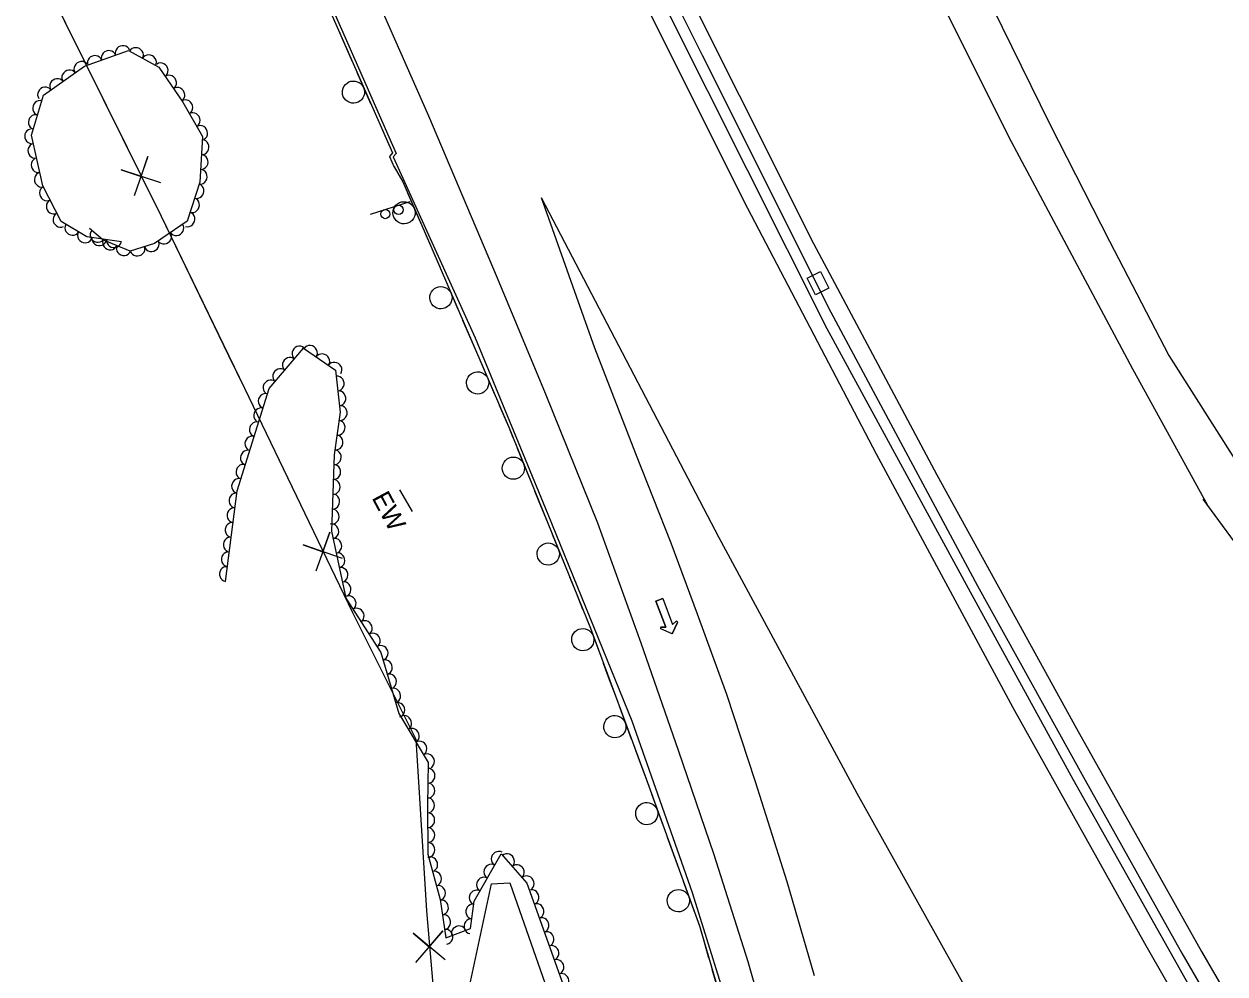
# Model space of a CAD drawing. Extents: x 1746719 to 1766531, y 631721 to 662391.
# Drawn here: x 1764151.5 to 1764475.4, y 633278.6 to 633534.8 of the extents above; entities that cross this region are included whole.
import ezdxf

# ---------------------------------------------------------------- set-up
doc = ezdxf.new("R2010")
doc.units = 0
for name, color, linetype in [('SURVEY - AERIAL SURVEY - Photo Control - Points - Elevations', 7, 'Continuous'), ('SURVEY - AERIAL SURVEY - Photo Control - Points - Locators', 7, 'Continuous'), ('SURVEY - AERIAL SURVEY - Photo Control - Points - Numbers', 7, 'Continuous'), ('SURVEY - AERIAL SURVEY - Photo Control with Text', 7, 'Continuous'), ('SURVEY - CENTERLINE - Existing Roads Curve Text', 7, 'Continuous'), ('SURVEY - CENTERLINE - Existing Roads Text', 7, 'Continuous'), ('SURVEY - CENTERLINE - Preliminary - Development', 7, 'Continuous'), ('SURVEY - CENTERLINE - Preliminary Curve Text', 7, 'Continuous'), ('SURVEY - CONTROL - Grid', 7, 'Continuous')]:
    doc.layers.add(name, color=color, linetype=linetype)

msp = doc.modelspace()

# ---------------------------------------------------------------- linework, layer by layer
at = {"layer": 'SURVEY - AERIAL SURVEY - Photo Control - Points - Elevations'}
for points in [[(1764348.8, 633669.24), (1764389.59, 633586.37), (1764428.15, 633507.81), (1764444.24, 633476.22), (1764460.26, 633445.38)], [(1764180.93, 633660.56), (1764237.06, 633533.45), (1764251.85, 633499.9), (1764251.04, 633498.94), (1764273.17, 633450.19), (1764292.77, 633402.64), (1764315.39, 633346.9), (1764331.65, 633300.6), (1764347.14, 633250.91), (1764359.02, 633206.16), (1764363.95, 633185.33), (1764368.51, 633162.04), (1764371.67, 633132.89), (1764372.54, 633100.95), (1764372.37, 633061.95), (1764369.93, 633023.67), (1764365.45, 632984.07)], [(1764340.8, 633658.6), (1764378.13, 633582.34), (1764417.77, 633503.15), (1764450.46, 633441.79), (1764470.69, 633405.08)], [(1764286.91, 633632.22), (1764324.36, 633555.72), (1764364.46, 633475.61), (1764397.7, 633413.21), (1764435.38, 633344.82), (1764469.06, 633284.69), (1764504.2, 633224.1), (1764542.48, 633159.48), (1764578.77, 633099.35), (1764616.47, 633039.95), (1764651.83, 632984.84), (1764692.24, 632923.64), (1764727.21, 632872.71), (1764758.15, 632827.22), (1764788.79, 632783.76), (1764825.53, 632732.1), (1764845.75, 632704.38)], [(1764831.69, 632702.44), (1764811.98, 632730.49), (1764779.64, 632775.81), (1764755.56, 632810.46), (1764723.74, 632856.23), (1764690.96, 632904.23), (1764661.37, 632949.17), (1764640.02, 632981.61), (1764615.9, 633018.34), (1764577.35, 633078.68), (1764534.79, 633147.94), (1764491.74, 633220.52), (1764453.8, 633286.81), (1764418.29, 633350.37), (1764381.37, 633418.77), (1764346.73, 633485.01), (1764310.57, 633557.37), (1764276.55, 633626.71)], [(1764375.62, 633017.64), (1764377.11, 633036.06), (1764378.16, 633054.7), (1764378.58, 633076.59), (1764378.28, 633098.77), (1764377.03, 633120.24), (1764375.76, 633139.47), (1764373.54, 633158.27), (1764370.32, 633178.81), (1764365.78, 633204.96), (1764360.5, 633229.86), (1764354.37, 633255.4), (1764346.8, 633281.9), (1764337.58, 633310.69), (1764327.99, 633338.84), (1764317.96, 633367.8), (1764306.25, 633400.14), (1764292.1, 633435.15), (1764279.15, 633466.29), (1764260.67, 633509.91), (1764240.97, 633554.63), (1764224.98, 633591.65)], [(1764364.68, 633278.08), (1764357.33, 633303.48), (1764348.81, 633330.39), (1764341.06, 633353.93), (1764333.11, 633375.62), (1764326, 633394.77), (1764316.48, 633418.88), (1764305.41, 633447.36), (1764291.02, 633487.95)], [(1764777.7, 632695.9), (1764740.39, 632748.17), (1764716.15, 632783.07), (1764684.21, 632828.99), (1764651.09, 632877.5), (1764621.28, 632922.78), (1764599.91, 632955.24), (1764575.61, 632992.25), (1764536.68, 633053.19), (1764493.7, 633123.13), (1764450.26, 633196.35), (1764412.02, 633263.19), (1764376.22, 633327.26), (1764338.98, 633396.24), (1764291.02, 633487.95)], [(1764460.26, 633445.38), (1764503.08, 633378.08)], [(1764563.3, 633279.03), (1764469.51, 633406.68)]]:
    msp.add_lwpolyline(points, dxfattribs=at)
at = {"layer": 'SURVEY - AERIAL SURVEY - Photo Control - Points - Locators'}
for p, q in [((1764321.92, 633379.17), (1764323.76, 633379.86)), ((1764323.76, 633379.86), (1764321.92, 633379.17)), ((1764324.58, 633372.13), (1764321.92, 633379.17)), ((1764321.92, 633379.17), (1764324.58, 633372.13)), ((1764323.76, 633379.86), (1764326.42, 633372.83)), ((1764323.76, 633379.86), (1764326.42, 633372.83)), ((1764323.35, 633372.17), (1764324.58, 633372.13)), ((1764324.58, 633372.13), (1764323.35, 633372.17)), ((1764327.71, 633373.39), (1764326.32, 633370.31)), ((1764326.32, 633370.31), (1764327.71, 633373.39)), ((1764326.42, 633372.83), (1764327.32, 633373.67)), ((1764326.42, 633372.83), (1764327.32, 633373.67)), ((1764326.32, 633370.31), (1764323.25, 633371.7)), ((1764326.32, 633370.31), (1764323.25, 633371.7))]:
    msp.add_line(p, q, dxfattribs=at)
msp.add_lwpolyline([(1764217.52, 632950.86), (1764233.96, 633053.68), (1764238.22, 633178.73), (1764251.95, 633231.92), (1764269.77, 633266.37), (1764277.54, 633302.92), (1764282.55, 633303.21), (1764295.22, 633266.91), (1764297.88, 633268.26), (1764313.8, 633246.32), (1764333.81, 633245.93), (1764340.96, 633234.86), (1764349.07, 633222.31), (1764363.07, 633166.36), (1764365.96, 633113.65), (1764366.58, 633060.3), (1764362.57, 633002.69)], dxfattribs=at)
for centre, start, end in [((1764323.35, 633371.92), 88.2612, 245.7095), ((1764323.35, 633371.92), 88.2612, 245.7095), ((1764327.49, 633373.49), 335.7095, 133.2026), ((1764327.49, 633373.49), 335.7095, 133.2026)]:
    msp.add_arc(centre, 0.246, start, end, dxfattribs=at)
at = {"layer": 'SURVEY - AERIAL SURVEY - Photo Control - Points - Numbers'}
for points in [[(1764180.13, 633660.21), (1764236.26, 633533.1), (1764250.83, 633500.04), (1764250.02, 633499.07), (1764251.32, 633496.19)], [(1764837.81, 632703.35), (1764810.72, 632740.31), (1764770.99, 632796.4), (1764726.66, 632860.1), (1764677.61, 632931.8), (1764621.09, 633019), (1764574.03, 633093.64), (1764526.02, 633172.29), (1764474.29, 633260.27), (1764434.46, 633331.05), (1764406.76, 633381.58), (1764368.12, 633452.62), (1764325.13, 633538.21), (1764281.43, 633628.12)], [(1764283.41, 633629.46), (1764296.35, 633602.51), (1764334.35, 633526.38), (1764369.12, 633457.05), (1764408.67, 633383.28), (1764437.22, 633331.71), (1764463.82, 633284.24), (1764490.85, 633237.46), (1764535.54, 633161.37), (1764569.37, 633106.49), (1764606.28, 633047.19), (1764645.68, 632986.22), (1764676.08, 632939.9), (1764709.83, 632889.53), (1764732.42, 632856.58), (1764758.21, 632819.17), (1764787.18, 632777.39), (1764806.45, 632750.71), (1764840.69, 632703.63)], [(1764236.16, 633533.34), (1764236.26, 633533.1), (1764238.05, 633529.04)], [(1764238.05, 633529.04), (1764239.95, 633524.73)], [(1764241.24, 633521.81), (1764244.95, 633513.39)], [(1764246.24, 633510.46), (1764248.13, 633506.16)], [(1764248.13, 633506.16), (1764250.03, 633501.86)], [(1764250.04, 633499.11), (1764250.02, 633499.08), (1764251.32, 633496.19)], [(1764251.28, 633496.28), (1764253.61, 633492.24), (1764261.18, 633474.91), (1764282.22, 633426.03), (1764304.24, 633371.87), (1764319.24, 633331.22), (1764333.63, 633291.54), (1764344.61, 633253.99), (1764354.34, 633219.42), (1764359.53, 633197.55), (1764364.8, 633173.55), (1764367.86, 633154.62), (1764369.32, 633137.18), (1764371, 633110.32), (1764371.64, 633083.85), (1764371.62, 633060.38), (1764370, 633036.65), (1764367.74, 633012.27)], [(1764251.28, 633496.28), (1764253.61, 633492.24), (1764253.62, 633492.2)], [(1764254.9, 633489.27), (1764258.59, 633480.84)], [(1764259.87, 633477.91), (1764261.18, 633474.91), (1764261.75, 633473.6)], [(1764261.75, 633473.6), (1764263.6, 633469.28)], [(1764264.87, 633466.34), (1764268.51, 633457.89)], [(1764269.77, 633454.95), (1764271.63, 633450.64)], [(1764271.63, 633450.64), (1764273.49, 633446.32)], [(1764274.75, 633443.38), (1764278.39, 633434.93)], [(1764279.65, 633431.99), (1764281.51, 633427.67)], [(1764281.51, 633427.67), (1764282.22, 633426.03), (1764283.32, 633423.33)], [(1764284.52, 633420.37), (1764287.99, 633411.84)], [(1764289.19, 633408.88), (1764290.96, 633404.53)], [(1764290.96, 633404.53), (1764292.73, 633400.17)], [(1764293.94, 633397.21), (1764297.4, 633388.69)], [(1764298.61, 633385.72), (1764300.38, 633381.37)], [(1764300.38, 633381.37), (1764302.15, 633377.01)], [(1764303.35, 633374.05), (1764304.24, 633371.87), (1764306.61, 633365.45)], [(1764307.72, 633362.44), (1764309.34, 633358.03)], [(1764309.34, 633358.03), (1764310.97, 633353.62)], [(1764312.08, 633350.62), (1764315.27, 633341.99)], [(1764316.37, 633338.99), (1764318, 633334.58)], [(1764318, 633334.58), (1764319.24, 633331.22), (1764319.62, 633330.17)], [(1764320.71, 633327.16), (1764323.85, 633318.51)], [(1764324.94, 633315.5), (1764326.54, 633311.08)], [(1764326.54, 633311.08), (1764328.15, 633306.67)], [(1764329.24, 633303.66), (1764332.37, 633295.01)], [(1764333.46, 633292), (1764333.63, 633291.54), (1764334.81, 633287.5)], [(1764334.81, 633287.5), (1764336.13, 633282.99)], [(1764337.03, 633279.92), (1764339.61, 633271.09)]]:
    msp.add_lwpolyline(points, dxfattribs=at)
for centre, start, end in [((1764240.33, 633516.43), 137.0484, 137.0344), ((1764253.98, 633483.89), 136.8821, 136.8681), ((1764263.91, 633460.97), 136.5547, 136.5408), ((1764273.8, 633438.01), 136.5547, 136.5408), ((1764283.46, 633415.02), 135.3926, 135.3786), ((1764292.87, 633391.86), 135.3926, 135.3786), ((1764302.19, 633368.76), 133.5282, 133.5142), ((1764310.84, 633345.31), 133.5282, 133.5142), ((1764319.45, 633321.86), 133.2013, 133.1873), ((1764327.97, 633298.35), 133.2013, 133.1873)]:
    msp.add_arc(centre, 3, start, end, dxfattribs=at)
at = {"layer": 'SURVEY - AERIAL SURVEY - Photo Control with Text'}
for points in [[(1764177.71, 633476.1), (1764168.44, 633477.37), (1764161.45, 633481.53), (1764156.52, 633491.16), (1764153.47, 633504.81), (1764156.75, 633515.62), (1764167.8, 633523.42), (1764179.6, 633527.63), (1764187.86, 633523.12), (1764194.29, 633513.7), (1764199.63, 633504.46), (1764198.87, 633492.14), (1764195.48, 633481.65), (1764186.66, 633475.59), (1764180.11, 633473.52), (1764172.75, 633476.59), (1764169.12, 633479.63)], [(1764205.81, 633384.48), (1764208.96, 633408.94), (1764217.59, 633436.47), (1764226.88, 633447.39), (1764235.52, 633441.46), (1764236.77, 633430.14), (1764235.15, 633418.62), (1764234.44, 633398.06), (1764238.26, 633379.96), (1764247.74, 633365.27), (1764252.55, 633348.89), (1764260.47, 633335.63), (1764260.31, 633324.09), (1764260.4, 633310.87), (1764263.71, 633298.68), (1764265.28, 633288.34), (1764271.93, 633290.88), (1764272.88, 633298.21), (1764280.16, 633310.97), (1764287.12, 633303.1), (1764298.26, 633271.93)]]:
    msp.add_lwpolyline(points, dxfattribs=at)
for centre, major_axis in [((1764174.29, 633525.74), (1.88, 0.67)), ((1764178.05, 633527.08), (1.88, 0.67)), ((1764181.67, 633526.5), (1.76, -0.96)), ((1764166.89, 633522.78), (1.63, 1.15)), ((1764170.52, 633524.39), (1.88, 0.67)), ((1764185.18, 633524.58), (1.76, -0.96)), ((1764188.4, 633522.34), (1.13, -1.65)), ((1764163.62, 633520.47), (1.63, 1.15)), ((1764190.65, 633519.04), (1.13, -1.65)), ((1764157.09, 633515.86), (1.63, 1.15)), ((1764160.36, 633518.16), (1.63, 1.15)), ((1764192.91, 633515.73), (1.13, -1.65)), ((1764195.06, 633512.37), (1, -1.73)), ((1764155.71, 633512.18), (0.58, 1.91)), ((1764154.55, 633508.36), (0.58, 1.91)), ((1764197.06, 633508.9), (1, -1.73)), ((1764153.53, 633504.52), (-0.44, 1.95)), ((1764199.06, 633505.44), (1, -1.73)), ((1764154.41, 633500.62), (-0.44, 1.95)), ((1764199.45, 633501.6), (-0.12, -2)), ((1764155.28, 633496.72), (-0.44, 1.95)), ((1764199.21, 633497.6), (-0.12, -2)), ((1764198.96, 633493.61), (-0.12, -2)), ((1764156.15, 633492.81), (-0.44, 1.95)), ((1764157.57, 633489.11), (-0.91, 1.78)), ((1764198.1, 633489.74), (-0.62, -1.9)), ((1764159.39, 633485.55), (-0.91, 1.78)), ((1764196.87, 633485.93), (-0.62, -1.9)), ((1764161.21, 633481.99), (-0.91, 1.78)), ((1764195.64, 633482.13), (-0.62, -1.9)), ((1764164.45, 633479.75), (-1.72, 1.02)), ((1764171.25, 633477.85), (-1.53, 1.28)), ((1764192.6, 633479.67), (-1.65, -1.13)), ((1764167.88, 633477.7), (-1.72, 1.02)), ((1764171.76, 633476.91), (-1.98, 0.27)), ((1764174.64, 633475.8), (-1.85, 0.77)), ((1764175.72, 633476.37), (-1.98, 0.27)), ((1764185.9, 633475.35), (-1.91, -0.6)), ((1764189.3, 633477.41), (-1.65, -1.13)), ((1764178.33, 633474.26), (-1.85, 0.77)), ((1764182.08, 633474.14), (-1.91, -0.6)), ((1764225.68, 633445.98), (1.3, 1.52)), ((1764228.65, 633446.18), (1.65, -1.13)), ((1764223.09, 633442.93), (1.3, 1.52)), ((1764231.95, 633443.91), (1.65, -1.13)), ((1764235.24, 633441.65), (1.65, -1.13)), ((1764220.49, 633439.89), (1.3, 1.52)), ((1764217.9, 633436.84), (1.3, 1.52)), ((1764235.92, 633437.82), (0.22, -1.99)), ((1764216.54, 633433.12), (0.6, 1.91)), ((1764236.36, 633433.84), (0.22, -1.99)), ((1764215.34, 633429.3), (0.6, 1.91)), ((1764236.73, 633429.87), (-0.28, -1.98)), ((1764214.14, 633425.48), (0.6, 1.91)), ((1764236.18, 633425.91), (-0.28, -1.98)), ((1764235.62, 633421.95), (-0.28, -1.98)), ((1764212.95, 633421.66), (0.6, 1.91)), ((1764211.75, 633417.85), (0.6, 1.91)), ((1764235.13, 633417.98), (-0.07, -2)), ((1764210.55, 633414.03), (0.6, 1.91)), ((1764234.99, 633413.98), (-0.07, -2)), ((1764209.36, 633410.21), (0.6, 1.91)), ((1764234.85, 633409.98), (-0.07, -2)), ((1764208.62, 633406.3), (0.25, 1.98)), ((1764234.71, 633405.99), (-0.07, -2)), ((1764208.11, 633402.33), (0.25, 1.98)), ((1764234.58, 633401.99), (-0.07, -2)), ((1764207.6, 633398.36), (0.25, 1.98)), ((1764234.45, 633397.99), (0.41, -1.96)), ((1764207.09, 633394.4), (0.25, 1.98)), ((1764235.28, 633394.08), (0.41, -1.96)), ((1764206.58, 633390.43), (0.25, 1.98)), ((1764236.1, 633390.17), (0.41, -1.96)), ((1764206.07, 633386.46), (0.25, 1.98)), ((1764236.93, 633386.25), (0.41, -1.96)), ((1764237.76, 633382.34), (0.41, -1.96)), ((1764239.11, 633378.64), (1.08, -1.68)), ((1764241.28, 633375.28), (1.08, -1.68)), ((1764243.45, 633371.92), (1.08, -1.68)), ((1764245.62, 633368.56), (1.08, -1.68)), ((1764247.76, 633365.19), (0.56, -1.92)), ((1764248.89, 633361.35), (0.56, -1.92)), ((1764250.02, 633357.51), (0.56, -1.92)), ((1764251.14, 633353.67), (0.56, -1.92)), ((1764252.27, 633349.84), (0.56, -1.92)), ((1764254.09, 633346.3), (1.03, -1.72)), ((1764256.15, 633342.87), (1.03, -1.72)), ((1764258.2, 633339.43), (1.03, -1.72)), ((1764260.25, 633336), (1.03, -1.72)), ((1764260.42, 633332.06), (-0.03, -2)), ((1764260.37, 633328.06), (-0.03, -2)), ((1764260.31, 633324.06), (0.01, -2)), ((1764260.34, 633320.06), (0.01, -2)), ((1764260.37, 633316.06), (0.01, -2)), ((1764260.39, 633312.06), (0.01, -2)), ((1764279.42, 633309.68), (0.99, 1.74)), ((1764281.82, 633309.09), (1.32, -1.5)), ((1764261.14, 633308.16), (0.52, -1.93)), ((1764277.44, 633306.2), (0.99, 1.74)), ((1764284.47, 633306.1), (1.32, -1.5)), ((1764262.19, 633304.3), (0.52, -1.93)), ((1764275.46, 633302.73), (0.99, 1.74)), ((1764287.12, 633303.1), (1.32, -1.5)), ((1764263.23, 633300.44), (0.52, -1.93)), ((1764273.48, 633299.25), (0.99, 1.74)), ((1764288.47, 633299.33), (0.67, -1.88)), ((1764264.04, 633296.53), (0.3, -1.98)), ((1764272.52, 633295.44), (0.26, 1.98)), ((1764289.81, 633295.57), (0.67, -1.88)), ((1764264.64, 633292.57), (0.3, -1.98)), ((1764268.75, 633289.66), (1.87, 0.71)), ((1764272.01, 633291.47), (0.26, 1.98)), ((1764291.16, 633291.8), (0.67, -1.88)), ((1764265.24, 633288.62), (0.3, -1.98)), ((1764292.51, 633288.03), (0.67, -1.88)), ((1764293.85, 633284.27), (0.67, -1.88)), ((1764295.2, 633280.5), (0.67, -1.88)), ((1764296.54, 633276.73), (0.67, -1.88))]:
    msp.add_ellipse(centre, major_axis=major_axis, ratio=0.940188, start_param=0, end_param=3.141593, dxfattribs=at)
at = {"layer": 'SURVEY - CENTERLINE - Existing Roads Curve Text'}
for points in [[(1764157.08, 633546.35), (1764188.43, 633483.01), (1764210.92, 633436.55), (1764240.06, 633376.12), (1764257.15, 633341.97), (1764260.03, 633295.61), (1764263.15, 633259.05), (1764266.69, 633201.88), (1764280.11, 633068.17), (1764276.46, 633025.64)], [(1764157.08, 633546.35), (1764179.26, 633501.54)], [(1764188.34, 633491.97), (1764177.67, 633495.51), (1764183.03, 633493.69), (1764184.84, 633499.05), (1764181.17, 633488.42)], [(1764186.4, 633487.11), (1764188.43, 633483.01), (1764206.65, 633445.36)], [(1764206.65, 633445.36), (1764210.92, 633436.55), (1764228.38, 633400.33)], [(1764237.37, 633390.67), (1764226.73, 633394.32), (1764232.07, 633392.45), (1764233.94, 633397.79), (1764230.16, 633387.2)], [(1764235.38, 633385.83), (1764240.06, 633376.12), (1764256, 633344.26)], [(1764256, 633344.26), (1764257.15, 633341.97), (1764260.03, 633295.61), (1764260.11, 633294.63)], [(1764265.07, 633282.41), (1764256.43, 633289.6), (1764260.75, 633285.95), (1764264.4, 633290.28), (1764257.1, 633281.72)]]:
    msp.add_lwpolyline(points, dxfattribs=at)
at = {"layer": 'SURVEY - CENTERLINE - Existing Roads Text'}
msp.add_lwpolyline([(1764252.7, 633409.2), (1764256.17, 633403.35)], dxfattribs=at)
at = {"layer": 'SURVEY - CENTERLINE - Preliminary Curve Text'}
msp.add_line((1764365.64, 633464.92), (1764365.64, 633464.92), dxfattribs=at)
msp.add_lwpolyline([(1764362.73, 633466.24), (1764366.29, 633468.05), (1764368.56, 633463.6), (1764364.99, 633461.78), (1764362.73, 633466.24)], dxfattribs=at)
at = {"layer": 'SURVEY - CONTROL - Grid'}
msp.add_line((1764244.91, 633483.56), (1764255.58, 633486.95), dxfattribs=at)
for centre in [(1764252.49, 633484.68), (1764248.92, 633483.55)]:
    msp.add_circle(centre, 1.25, dxfattribs=at)

# ---------------------------------------------------------------- texts
at = {"layer": 'SURVEY - CENTERLINE - Preliminary - Development'}
msp.add_text('EW', height=5, rotation=298.1824, dxfattribs=at).set_placement((1764245.16, 633407.04))

doc.saveas('drawing.dxf')
